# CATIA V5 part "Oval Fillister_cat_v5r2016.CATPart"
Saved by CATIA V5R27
Part number: Oval Fillister
Bounding box of the stored display mesh (mm): x -6 to 6, y -6 to 6, z -7 to 4
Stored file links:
  E:\_Deepak\2017_Deepak\CATIA\Resources\Tutorial Files\Tutorials\c13_catia_v5_6r2016_tut\c13tut2\c13tut02.CATParts\Oval Fillister_cat_v5r2016.CATPart
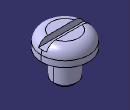
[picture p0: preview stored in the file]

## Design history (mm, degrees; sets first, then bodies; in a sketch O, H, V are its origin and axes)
Body1 (main body)
  Sketch1 on xy-plane, origin (0, 0, 0), H (1, 0, 0), V (0, 1, 0)
    circle A1 centre (0, 0) radius 6
    radius A1 = 6
  Pad1: profile Sketch1, direction (0, 0, 1), length 4
  Sketch2 on face of Pad1, origin (0, 0, 0), H (1, 0, 0), V (0, -1, 0)
    circle A1 centre (0, 0) radius 3
    radius A1 = 3
  Pad2: profile Sketch2, direction (0, 0, -1), length 6
  Sketch3 on face of Pad2, origin (0, 0, -6), H (1, 0, 0), V (0, -1, 0)
    circle A1 centre (0, 0) radius 2
    radius A1 = 2
  Pad3: profile Sketch3, direction (0, 0, -1), length 1
  Fillet1: radius 2.5, on 1 edge
  Sketch4 on yz-plane, origin (0, 0, 0), H (0, 1, 0), V (0, 0, 1)
    line L1 (-1, 4.5549) -> (1, 4.5549)
    line L2 (1, 4.5549) -> (1, 2.5)
    line L3 (1, 2.5) -> (-1, 2.5)
    line L4 (-1, 2.5) -> (-1, 4.5549)
    distance H L3 = 2.5
    distance L2 V = 1
    length L1 = 2
    horizontal: L1 H, L3 H
    vertical: L2 V, L4 V
  Pocket1: profile Sketch4, direction (-1, 0, 0), length 8, mirrored extent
